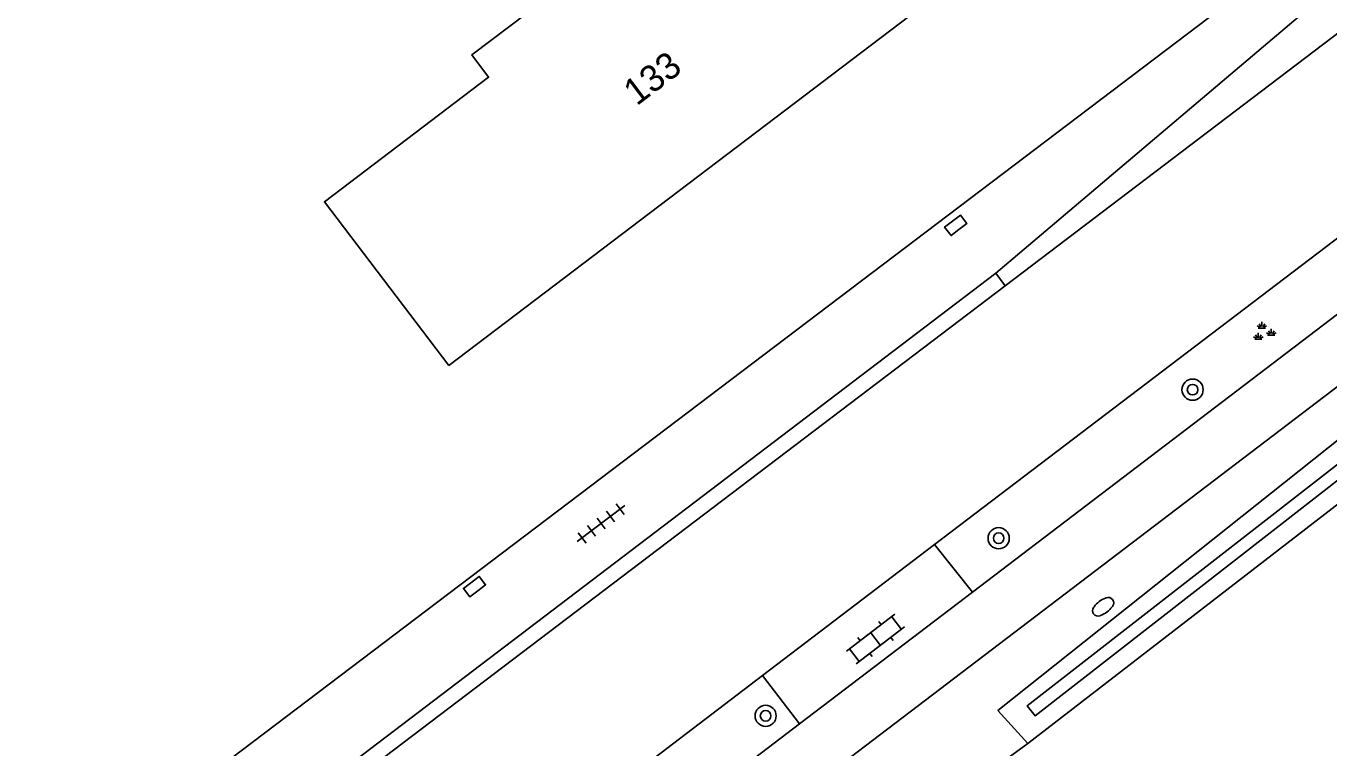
# Model space of a CAD drawing. Extents: x 137000 to 140001, y 403500 to 406000.
# Drawn here: x 139273.89 to 139323.07, y 403723.73 to 403750.96 of the extents above; entities that cross this region are included whole.
import ezdxf

# ---------------------------------------------------------------- set-up
doc = ezdxf.new("R2010")
doc.units = 0
for name, color, linetype in [('gg-anno-huisnummerreeks BGT', 7, 'Continuous'), ('gg-bbg-hoofdgebouw', 7, 'Continuous'), ('gg-knt-verharding', 7, 'Continuous'), ('gg-kntw-bovenkant insteek waterloop', 7, 'Continuous'), ('gg-kntw-waterlijn', 7, 'Continuous'), ('gt-grn-groengrens', 7, 'Continuous'), ('gt-grn-weggrens', 7, 'Continuous'), ('gt-symb-boom', 7, 'Continuous'), ('gt-symb-brandkraan', 7, 'Continuous'), ('gt-symb-groenvak', 7, 'Continuous'), ('gt-symb-klinker verharding', 7, 'Continuous'), ('gt-symb-kolk', 7, 'Continuous'), ('gt-symb-tegel verharding', 7, 'Continuous')]:
    doc.layers.add(name, color=color, linetype=linetype)

# ---------------------------------------------------------------- blocks, each defined once
blk = doc.blocks.new('gt0-KOLK')
at = {"layer": 'gt-symb-kolk'}
blk.add_lwpolyline([(0, 0), (0.375, 0), (0.375, 0.4), (-0.375, 0.4), (-0.375, 0), (0, 0)], dxfattribs=at)
blk = doc.blocks.new('gt0-BOOM')
at = {"layer": 'gt-symb-boom'}
for radius in [0.4, 0.2]:
    blk.add_circle((0, 0), radius, dxfattribs=at)
blk = doc.blocks.new('gt0-TEG1')
at = {"layer": 'gt-symb-tegel verharding'}
for p, q in [((-1.125, 0), (1.125, 0)), ((-0.9, -0.25), (-0.9, 0.25)), ((-0.45, -0.25), (-0.45, 0.25)), ((0, -0.25), (0, 0.25)), ((0.45, -0.25), (0.45, 0.25)), ((0.9, -0.25), (0.9, 0.25))]:
    blk.add_line(p, q, dxfattribs=at)
blk = doc.blocks.new('gt0-GRVAK')
at = {"layer": 'gt-symb-groenvak'}
for p, q in [((-0.11, 0.189), (-0.228, 0.24)), ((-0.182, 0.153), (0.088, 0.153)), ((-0.091, 0.211), (-0.156, 0.322)), ((-0.047, 0.214), (-0.047, 0.393)), ((-0.004, 0.211), (0.061, 0.322)), ((0.015, 0.189), (0.133, 0.24)), ((0.262, -0.052), (0.197, 0.059)), ((0.305, -0.049), (0.305, 0.13)), ((0.349, -0.052), (0.414, 0.059)), ((-0.245, -0.228), (-0.363, -0.177)), ((-0.318, -0.264), (-0.047, -0.264)), ((-0.226, -0.206), (-0.291, -0.095)), ((-0.183, -0.203), (-0.183, -0.024)), ((-0.139, -0.206), (-0.074, -0.095)), ((-0.12, -0.228), (-0.002, -0.177)), ((0.243, -0.074), (0.125, -0.023)), ((0.17, -0.11), (0.441, -0.11)), ((0.368, -0.074), (0.486, -0.023))]:
    blk.add_line(p, q, dxfattribs=at)
blk = doc.blocks.new('gt0-KL1')
at = {"layer": 'gt-symb-klinker verharding'}
for p, q in [((-1.15, 0.3), (1.15, 0.3)), ((-1, -0.3), (-1, 0.3)), ((-0.5, 0.3), (-0.5, 0.45)), ((0, -0.3), (0, 0.3)), ((0.5, 0.3), (0.5, 0.45)), ((1, -0.3), (1, 0.3)), ((-1.15, -0.3), (1.15, -0.3)), ((-0.5, -0.45), (-0.5, -0.3)), ((0.5, -0.45), (0.5, -0.3))]:
    blk.add_line(p, q, dxfattribs=at)
blk = doc.blocks.new('gt0-BR')
at = {"layer": 'gt-symb-brandkraan'}
for centre, radius, start, end in [((-0.244, 0), 0.206, 107.5669, 252.4331), ((0.599, -2.664), 3, 106.892, 107.5669), ((0, -0.691), 0.938, 73.108, 106.892), ((-0.599, -2.664), 3, 72.4331, 73.108), ((0.244, 0), 0.206, 287.567, 72.4331), ((0.599, 2.664), 3, 252.4331, 253.108), ((0, 0.691), 0.938, 253.108, 286.8921), ((-0.599, 2.664), 3, 286.8921, 287.567)]:
    blk.add_arc(centre, radius, start, end, dxfattribs=at)

msp = doc.modelspace()

# ---------------------------------------------------------------- linework, layer by layer
at = {"layer": 'gg-bbg-hoofdgebouw'}
for points in [[(139305.18, 403760.791), (139290.713, 403749.876), (139291.354, 403749.03), (139285.156, 403744.336), (139289.85, 403738.162)], [(139289.85, 403738.162), (139310.5, 403753.821), (139305.18, 403760.791)]]:
    msp.add_lwpolyline(points, dxfattribs=at)
at = {"layer": 'gg-knt-verharding'}
for p, q in [((139310.846, 403741.169), (139330.222, 403755.869)), ((139308.187, 403731.404), (139331.64, 403749.241)), ((139333.05, 403747.441), (139309.612, 403729.609)), ((139310.494, 403741.647), (139310.846, 403741.169)), ((139281.831, 403719.155), (139310.846, 403741.169)), ((139301.691, 403726.463), (139308.187, 403731.404)), ((139309.612, 403729.609), (139308.187, 403731.404)), ((139309.612, 403729.609), (139303.09, 403724.647)), ((139262.904, 403696.964), (139301.691, 403726.463)), ((139301.691, 403726.463), (139303.09, 403724.647)), ((139303.09, 403724.647), (139264.307, 403695.14))]:
    msp.add_line(p, q, dxfattribs=at)
for points in [[(139462.757, 403843.545), (139455.99, 403838.491), (139429.35, 403818.02), (139335.781, 403746.782), (139191.521, 403637.048)], [(139279.967, 403722.283), (139281.651, 403723.343), (139321.42, 403753.472), (139322.793, 403754.884)], [(139281.456, 403719.813), (139282.707, 403720.512), (139310.494, 403741.647)]]:
    msp.add_lwpolyline(points, dxfattribs=at)
at = {"layer": 'gg-kntw-bovenkant insteek waterloop'}
msp.add_line((139311.709, 403723.9), (139334.145, 403741.228), dxfattribs=at)
msp.add_lwpolyline([(139333.962, 403743.363), (139331.729, 403741.952), (139310.579, 403725.142), (139311.709, 403723.9)], dxfattribs=at)
at = {"layer": 'gg-kntw-waterlijn'}
msp.add_lwpolyline([(139334.406, 403742.793), (139330.776, 403740.176), (139311.685, 403725.324), (139311.978, 403724.948), (139325.344, 403735.346), (139332.1, 403740.492), (139334.605, 403742.216), (139334.862, 403741.782)], dxfattribs=at)
at = {"layer": 'gt-grn-groengrens'}
msp.add_line((139306.278, 403719.971), (139311.709, 403723.9), dxfattribs=at)
at = {"layer": 'gt-grn-weggrens'}
msp.add_line((139328.93, 403757.241), (139310.494, 403741.647), dxfattribs=at)

# ---------------------------------------------------------------- block references
at = {"layer": 'gt-symb-boom'}
for p in [(139317.925, 403737.247), (139310.605, 403731.644), (139301.808, 403724.944)]:
    msp.add_blockref('gt0-BOOM', p, dxfattribs=at)
at = {"layer": 'gt-symb-brandkraan', "rotation": -142.84362584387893}
msp.add_blockref('gt0-BR', (139314.546, 403729.059), dxfattribs=at)
at = {"layer": 'gt-symb-groenvak'}
msp.add_blockref('gt0-GRVAK', (139320.588, 403739.411), dxfattribs=at)
at = {"layer": 'gt-symb-klinker verharding', "rotation": 37.28225519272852}
msp.add_blockref('gt0-KL1', (139305.957, 403727.838), dxfattribs=at)
at = {"layer": 'gt-symb-kolk', "rotation": 37.44283634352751}
for p in [(139309.106, 403743.288), (139290.943, 403729.659)]:
    msp.add_blockref('gt0-KOLK', p, dxfattribs=at)
at = {"layer": 'gt-symb-tegel verharding', "rotation": 37.1563741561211}
msp.add_blockref('gt0-TEG1', (139295.595, 403732.195), dxfattribs=at)

# ---------------------------------------------------------------- texts
at = {"layer": 'gg-anno-huisnummerreeks BGT'}
msp.add_text('133', height=1, rotation=37.2, dxfattribs=at).set_placement((139296.94, 403747.93))

doc.saveas('drawing.dxf')
